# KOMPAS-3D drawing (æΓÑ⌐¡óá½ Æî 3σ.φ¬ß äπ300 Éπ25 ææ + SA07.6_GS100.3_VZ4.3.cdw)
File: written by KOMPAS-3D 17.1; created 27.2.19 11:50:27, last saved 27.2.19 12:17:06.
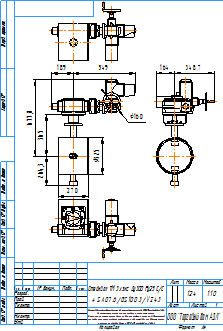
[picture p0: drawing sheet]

Sheet 1: A4, portrait

Title block, sheet 1: name: Стейнвал ТМ 3х.экс Ду300 Ру25 С/С / + SA07.6/GS100.3/VZ4.3; mass: 124; sheets: 1; sheet format: A4; stored path: C:\Users\kka\KOMPAS_Work\Дисковые повортные затворы ф. Boteli\Стейнвал + редуктор-привода\Стейнвал ТМ 3х.экс Ду700 Ру25 СС  + SA10.2_GS200.3_GZ200.3.cdw

Views: Вид 1, Проекционный вид 2, Проекционный вид 3, Проекционный вид 4
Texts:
  kka
  adl
  Рама для чертежей
  Лит-Масса-Масштаб
  Материал-Предприятие
  Масштаб
  Изм.
  Лист
  № докум.
  Подп.
  Дата
  Лит.
  Разраб.
  Пров.
  Т.контр.
  Листов
  Внимание! Данный продукт является объектом авторского права ООО «Торговый Дом АДЛ».
  Запрещается изменение, копирование, распространение
  (в том числе путем копирования на другие сайты и ресурсы в Интернете)
  или любое иное использование информации и объектов без предварительного
  согласия правообладателя (ООО «Торговый Дом АДЛ»).
  Н.контр.
  Утв.
  ООО "Торговый дом АДЛ"
  Изменение
  Номер документа
  Подпись
  Обозначение документа
  Наименование изделия
  Масса изделия по ГОСТ 2.109-73
  Порядковый номер листа
  Общее количество листов в документе
  Характер работы, выполненной лицом, подписавшим документ
  Наименование или индекс предприятия, выпускающего документ
  Инв. № подл.
  Подп. и дата
  Взам. инв. №
  Инв. № дубл.
  Инвентарный номер подлинника по ГОСТ 2.501-68
  Подпись принявшего подлинник в отдел технической документации
  Инвентарный номер подлинника, взамен которого выпущен данный подлинник
  Инвентарный номер дубликата по ГОСТ 2.502-68
  Подпись принявшего дубликат в отдел технической документации
  Справ. №
  Перв. примен.
  Обозначение документа, взамен или на основании которого выпущен данный документ
  Обозначение документа, в котором впервые записан данный документ
  Подпись лица, копировавшего чертеж
  Обозначение формата листа
  !Рама для чертежа
Dimensions and other numbers on the sheet: 160; 325; 365; 677,8; 264,3; 189; 549; 270; 348,7; 164; 1:10; 1; 124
